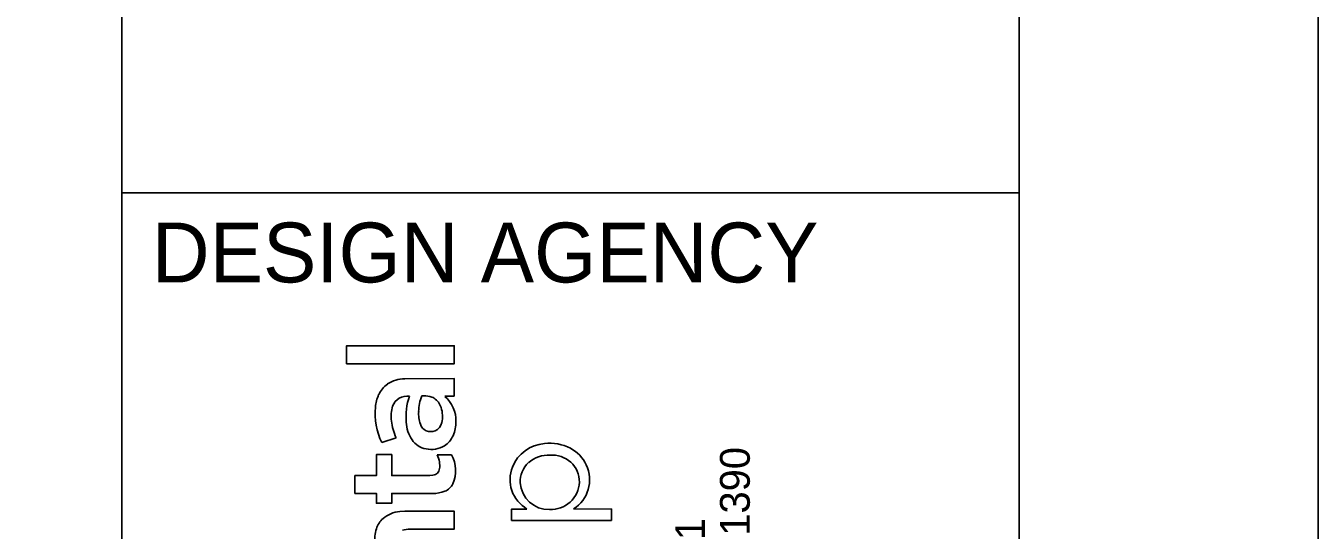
# Model space of a CAD drawing. Extents: x -0.6 to 34, y 0 to 22.
# Drawn here: x 31.839 to 34, y 3.936 to 4.779 of the extents above; entities that cross this region are included whole.
import ezdxf

# ---------------------------------------------------------------- set-up
doc = ezdxf.new("R2010")
doc.units = 0
for name, color, linetype in [('SH_Border', 7, 'Continuous'), ('SH_Cut_Line', 7, 'Continuous'), ('SH_Data', 7, 'Continuous')]:
    doc.layers.add(name, color=color, linetype=linetype)

msp = doc.modelspace()

# ---------------------------------------------------------------- linework, layer by layer
at = {"layer": 'SH_Border'}
for p, q in [((32, 0.5), (32, 21.5)), ((32, 4.5), (33.5, 4.5))]:
    msp.add_line(p, q, dxfattribs=at)
msp.add_lwpolyline([(1.5, 21.5), (33.5, 21.5), (33.5, 0.5), (1.5, 0.5)], close=True, dxfattribs=at)
at = {"layer": 'SH_Cut_Line'}
msp.add_lwpolyline([(0, 0), (34, 0), (34, 22), (0, 22)], close=True, dxfattribs=at)
at = {"layer": 'SH_Data'}
for p, q in [((32.3756, 4.2141), (32.3756, 4.244)), ((32.3756, 4.244), (32.5557, 4.244)), ((32.5557, 4.244), (32.5557, 4.2141)), ((32.5557, 4.2141), (32.3756, 4.2141)), ((32.4727, 4.189), (32.5555, 4.1892)), ((32.5555, 4.1892), (32.5557, 4.1596)), ((32.5557, 4.1596), (32.5397, 4.1596)), ((32.4582, 4.0904), (32.4343, 4.0823)), ((32.4254, 4.027), (32.4255, 4.0621)), ((32.4255, 4.0621), (32.4511, 4.0621)), ((32.4511, 4.0621), (32.4512, 4.027)), ((32.527, 4.0616), (32.5511, 4.0616)), ((32.3896, 3.9972), (32.3896, 4.027)), ((32.3896, 4.027), (32.4254, 4.027)), ((32.4512, 4.027), (32.515, 4.027)), ((32.515, 4.027), (32.52, 4.0275)), ((32.4254, 3.9972), (32.3896, 3.9972)), ((32.4254, 3.9807), (32.4254, 3.9972)), ((32.4511, 3.9807), (32.4254, 3.9807)), ((32.5197, 3.9972), (32.4511, 3.9972)), ((32.4511, 3.9972), (32.4511, 3.9807)), ((32.4644, 3.9669), (32.4729, 3.9673)), ((32.4729, 3.9673), (32.5557, 3.9673)), ((32.5557, 3.9673), (32.5557, 3.9375)), ((32.6515, 3.9521), (32.6515, 3.9711)), ((32.6515, 3.9711), (32.6771, 3.9711)), ((32.7549, 3.9713), (32.8186, 3.9711)), ((32.8186, 3.9711), (32.8184, 3.9521)), ((32.5557, 3.9375), (32.4814, 3.9375)), ((32.8184, 3.9521), (32.6515, 3.9521))]:
    msp.add_line(p, q, dxfattribs=at)
msp.add_lwpolyline([(32.3756, 4.2141), (32.3756, 4.244), (32.5557, 4.244), (32.5557, 4.2141)], close=True, dxfattribs=at)
for points in [[(32.4727, 4.189), (32.5555, 4.1892), (32.5557, 4.1596)], [(32.5557, 4.1596), (32.5397, 4.1596)], [(32.4582, 4.0904), (32.4343, 4.0823)], [(32.5197, 3.9972), (32.4511, 3.9972), (32.4511, 3.9807), (32.4254, 3.9807), (32.4254, 3.9972), (32.3896, 3.9972), (32.3896, 4.027), (32.4254, 4.027), (32.4255, 4.0621), (32.4511, 4.0621), (32.4512, 4.027), (32.515, 4.027), (32.52, 4.0275)], [(32.527, 4.0616), (32.5511, 4.0616)], [(32.4644, 3.9669), (32.4729, 3.9673), (32.5557, 3.9673), (32.5557, 3.9375), (32.4814, 3.9375)], [(32.7549, 3.9713), (32.8186, 3.9711), (32.8184, 3.9521), (32.6515, 3.9521)], [(32.6515, 3.9521), (32.6515, 3.9711), (32.6771, 3.9711)]]:
    msp.add_lwpolyline(points, dxfattribs=at)
for centre, radius, start, end in [((32.4685, 4.1447), 0.043, 124.537, 155.6594), ((32.4685, 4.1447), 0.043, 124.537, 155.6594), ((32.4745, 4.1326), 0.0565, 91.8942, 122.6317), ((32.4745, 4.1326), 0.0565, 91.8942, 122.6317), ((32.4882, 4.1361), 0.0646, 155.9764, 175.3149), ((32.4882, 4.1361), 0.0646, 155.9764, 175.3149), ((32.4753, 4.1356), 0.024, 119.4252, 161.6629), ((32.4753, 4.1356), 0.024, 119.4252, 161.6629), ((32.4779, 4.1278), 0.0321, 85.3802, 116.6222), ((32.4779, 4.1278), 0.0321, 85.3802, 116.6222), ((32.5879, 4.1251), 0.1129, 162.0821, 184.5285), ((32.5879, 4.1251), 0.1129, 162.0821, 184.5285), ((32.5801, 4.1313), 0.0841, 159.8366, 178.0362), ((32.5801, 4.1313), 0.0841, 159.8366, 178.0362), ((32.5051, 4.1074), 0.053, 79.6696, 94.2322), ((32.5051, 4.1074), 0.053, 79.6696, 94.2322), ((32.5089, 4.1364), 0.0238, 56.8913, 76.2149), ((32.5089, 4.1364), 0.0238, 56.8913, 76.2149), ((32.5052, 4.1318), 0.0297, 17.5984, 55.7282), ((32.5052, 4.1318), 0.0297, 17.5984, 55.7282), ((32.5055, 4.1191), 0.0529, 358.0746, 49.762), ((32.5055, 4.1191), 0.0529, 358.0746, 49.762), ((32.5364, 4.1308), 0.113, 174.6101, 205.3899), ((32.5364, 4.1308), 0.113, 174.6101, 205.3899), ((32.5076, 4.1265), 0.0576, 163.1369, 188.1675), ((32.5076, 4.1265), 0.0576, 163.1369, 188.1675), ((32.5466, 4.1303), 0.0506, 175.5903, 199.8857), ((32.5466, 4.1303), 0.0506, 175.5903, 199.8857), ((32.4916, 4.1264), 0.0443, 345.9408, 18.9919), ((32.4916, 4.1264), 0.0443, 345.9408, 18.9919), ((32.5473, 4.1297), 0.0973, 186.7598, 203.7981), ((32.5473, 4.1297), 0.0973, 186.7598, 203.7981), ((32.5328, 4.1187), 0.0575, 182.5676, 213.7144), ((32.5328, 4.1187), 0.0575, 182.5676, 213.7144), ((32.5164, 4.1189), 0.0184, 198.2844, 293.3081), ((32.5164, 4.1189), 0.0184, 198.2844, 293.3081), ((32.5152, 4.1199), 0.0199, 295.2883, 347.4639), ((32.5152, 4.1199), 0.0199, 295.2883, 347.4639), ((32.5019, 4.1168), 0.0566, 336.016, 0.5951), ((32.5019, 4.1168), 0.0566, 336.016, 0.5951), ((32.5149, 4.1078), 0.0366, 215.0668, 259.8133), ((32.5149, 4.1078), 0.0366, 215.0668, 259.8133), ((32.5175, 4.1097), 0.0394, 303.4436, 336.18), ((32.5175, 4.1097), 0.0394, 303.4436, 336.18), ((32.5175, 4.1131), 0.0423, 257.5256, 300.882), ((32.5175, 4.1131), 0.0423, 257.5256, 300.882), ((32.7108, 4.0182), 0.0624, 93.9866, 158.3119), ((32.7108, 4.0182), 0.0624, 93.9866, 158.3119), ((32.7156, 4.0065), 0.0746, 62.6889, 97.0135), ((32.7156, 4.0065), 0.0746, 62.6889, 97.0135), ((32.7212, 4.0191), 0.0608, 25.0657, 61.9602), ((32.7212, 4.0191), 0.0608, 25.0657, 61.9602), ((32.4863, 4.042), 0.0452, 10.1545, 25.723), ((32.4863, 4.042), 0.0452, 10.1545, 25.723), ((32.4957, 4.0436), 0.0356, 351.914, 10.2059), ((32.4957, 4.0436), 0.0356, 351.914, 10.2059), ((32.503, 4.0351), 0.0549, 336.589, 28.8991), ((32.503, 4.0351), 0.0549, 336.589, 28.8991), ((32.707, 4.0202), 0.0581, 158.656, 198.171), ((32.707, 4.0202), 0.0581, 158.656, 198.171), ((32.7092, 4.0167), 0.0434, 132.3289, 182.0949), ((32.7092, 4.0167), 0.0434, 132.3289, 182.0949), ((32.7138, 4.0102), 0.0513, 87.8965, 131.1812), ((32.7138, 4.0102), 0.0513, 87.8965, 131.1812), ((32.7175, 4.0102), 0.0513, 49.9089, 92.0363), ((32.7175, 4.0102), 0.0513, 49.9089, 92.0363), ((32.7215, 4.0173), 0.0433, 358.0487, 47.9447), ((32.7215, 4.0173), 0.0433, 358.0487, 47.9447), ((32.7245, 4.02), 0.0574, 301.9776, 25.6418), ((32.7245, 4.02), 0.0574, 301.9776, 25.6418), ((32.5184, 4.04), 0.0126, 277.6142, 353.7918), ((32.5184, 4.04), 0.0126, 277.6142, 353.7918), ((32.5209, 4.0486), 0.0514, 268.6727, 291.5235), ((32.5209, 4.0486), 0.0514, 268.6727, 291.5235), ((32.5291, 4.0261), 0.0275, 292.6889, 332.0598), ((32.5291, 4.0261), 0.0275, 292.6889, 332.0598), ((32.7103, 4.0243), 0.0627, 200.8399, 238.0162), ((32.7103, 4.0243), 0.0627, 200.8399, 238.0162), ((32.7135, 4.0181), 0.0478, 183.5974, 271.7045), ((32.7135, 4.0181), 0.0478, 183.5974, 271.7045), ((32.7172, 4.018), 0.0477, 267.3149, 357.4019), ((32.7172, 4.018), 0.0477, 267.3149, 357.4019), ((32.4635, 3.9255), 0.0402, 132.2238, 161.6823), ((32.4635, 3.9255), 0.0402, 132.2238, 161.6823), ((32.4687, 3.9172), 0.0499, 94.9706, 130.2248), ((32.4687, 3.9172), 0.0499, 94.9706, 130.2248), ((32.4787, 3.9211), 0.056, 162.274, 187.7917), ((32.4787, 3.9211), 0.056, 162.274, 187.7917), ((32.4811, 3.8915), 0.046, 89.6051, 105.3303), ((32.4811, 3.8915), 0.046, 89.6051, 105.3303)]:
    msp.add_arc(centre, radius, start, end, dxfattribs=at)

# ---------------------------------------------------------------- texts
msp.add_text('DESIGN AGENCY', height=0.1, dxfattribs=at).set_placement((32.05, 4.35))
for s, p in [('800.835.1390', (33.0497, 3.6671)), ('450 GRANT ST., AKRON, OH  44311', (32.9749, 2.8374))]:
    msp.add_text(s, height=0.049846, rotation=90, dxfattribs=at).set_placement(p)

doc.saveas('drawing.dxf')
